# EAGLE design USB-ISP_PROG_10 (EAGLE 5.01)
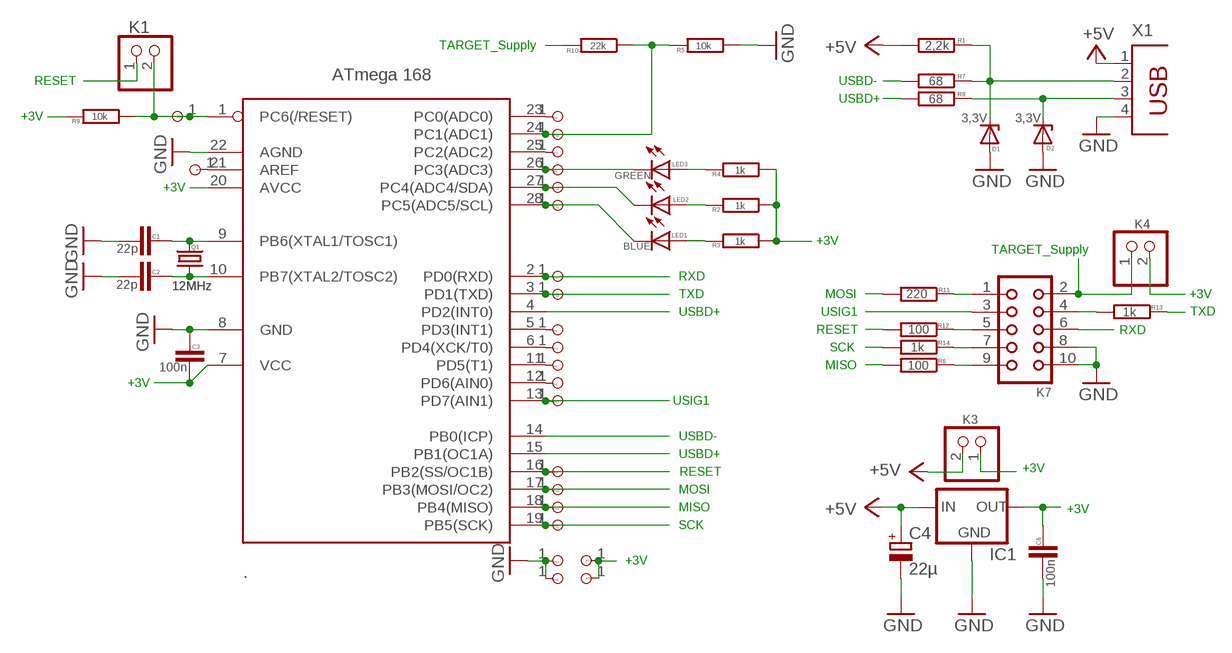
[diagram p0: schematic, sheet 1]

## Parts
.  ATmega 168  MEGA8-P  [DIL28-3]
C1  22p  C-EU025-024X044  [C025-024X044]
C2  22p  C-EU025-024X044  [C025-024X044]
C3  100n  C-EU025-024X044  [C025-024X044]
C4  22µ  CPOL-EU  [E2,5-11-L]
C6  100n  C-EU025-024X044  [C025-024X044]
D1  3,3V  ZENER-DIODEZD-7.5  [ZDIO-7.5]
D2  3,3V  ZENER-DIODEZD-7.5  [ZDIO-7.5]
IC1  78XXL-L  [78XXL-L]
JP1  PINHD-1X1  [1X01]
JP2  PINHD-1X1  [1X01]
JP3  PINHD-1X1  [1X01]
JP4  PINHD-1X1  [1X01]
JP5  PINHD-1X1  [1X01]
JP6  PINHD-1X1  [1X01]
JP7  PINHD-1X1  [1X01]
JP8  PINHD-1X1  [1X01]
JP9  PINHD-1X1  [1X01]
JP10  PINHD-1X1  [1X01]
JP11  PINHD-1X1  [1X01]
JP12  PINHD-1X1  [1X01]
JP13  PINHD-1X1  [1X01]
JP14  PINHD-1X1  [1X01]
JP15  PINHD-1X1  [1X01]
JP16  PINHD-1X1  [1X01]
JP17  PINHD-1X1  [1X01]
JP18  PINHD-1X1  [1X01]
JP19  PINHD-1X1  [1X01]
JP20  PINHD-1X1  [1X01]
JP21  PINHD-1X1  [1X01]
JP22  PINHD-1X1  [1X01]
JP23  PINHD-1X1  [1X01]
K1  PINHD-1X2  [1X02]
K3  PINHD-1X2  [1X02]
K4  PINHD-1X2  [1X02]
K7  CON10  [CON10]
LED1  BLUE  LED3MM  [LED3MM]
LED2  RED  LED3MM  [LED3MM]
LED3  GREEN  LED3MM  [LED3MM]
Q1  12MHz  CRYSTALHC49U70  [HC49U70]
R1  2,2k  R-EU_0207/07  [0207/07]
R2  1k  R-EU_0207/07  [0207/07]
R3  1k  R-EU_0207/07  [0207/07]
R4  1k  R-EU_0207/07  [0207/07]
R5  10k  R-EU_0207/07  [0207/07]
R6  100  R-EU_0207/07  [0207/07]
R7  68  R-EU_0207/07  [0207/07]
R8  68  R-EU_0207/07  [0207/07]
R9  10k  R-EU_0207/07  [0207/07]
R10  22k  R-EU_0207/07  [0207/07]
R11  220  R-EU_0207/07  [0207/07]
R12  100  R-EU_0207/17  [0207/17]
R13  1k  R-EU_0207/07  [0207/07]
R14  1k  R-EU_0207/07  [0207/07]
X1  PN87520-BKR  [PN87520-BKR]

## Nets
+3V: ..7(VCC) ..20(AVCC) C3.1 C6.2 IC1.OUT JP19.1 JP20.1 K3.1 K4.2 R2.1 R3.1 R4.1 R9.2
+5V: C4.+ IC1.IN K3.2 R1.2 X1.1
GND: ..8(GND) ..22(AGND) C1.1 C2.1 C3.2 C4.- C6.1 D1.A D2.A IC1.GND JP17.1 JP21.1 K7.8 K7.10 R5.1 X1.4
LED-BL: ..28(PC5(ADC5/SCL)) JP11.1 LED1.K(C)
LED-GN: ..26(PC3(ADC3)) JP9.1 LED3.K(C)
LED-RT: ..27(PC4(ADC4/SDA)) JP10.1 LED2.K(C)
MISO: ..18(PB4(MISO)) JP14.1 R6.2
MISO.: K7.9 R6.1
MOSI: ..17(PB3(MOSI/OC2)) JP13.1 R11.2
MOSI.: K7.1 R11.1
N$1: LED3.A R4.2
N$2: LED2.A R2.2
N$3: LED1.A R3.2
N$4: D1.C R1.1 R7.1 X1.2
N$5: D2.C R8.1 X1.3
N$13: ..23(PC0(ADC0)) JP1.1
N$14: ..9(PB6(XTAL1/TOSC1)) C1.2 Q1.2
N$15: ..10(PB7(XTAL2/TOSC2)) C2.2 Q1.1
N$16: ..1(PC6(/RESET)) JP18.1 K1.2 R9.1
N$17: ..25(PC2(ADC2)) JP2.1
N$18: ..24(PC1(ADC1)) JP16.1 R5.2 R10.1
N$19: ..5(PD3(INT1)) JP3.1
N$20: ..6(PD4(XCK/T0)) JP4.1
N$21: ..11(PD5(T1)) JP5.1
N$22: ..12(PD6(AIN0)) JP6.1
N$24: ..21(AREF) JP8.1
RESET: ..16(PB2(SS/OC1B)) JP7.1 K1.1 R12.2
RESET.: K7.5 R12.1
RXD: ..2(PD0(RXD)) JP22.1 K7.6
SCK: ..19(PB5(SCK)) JP15.1 R14.2
SCK.: K7.7 R14.1
TARGET_SUPPLY: K4.1 K7.2 R10.2
TXD: ..3(PD1(TXD)) JP23.1 R13.1
TXD,: K7.4 R13.2
USBD+: ..4(PD2(INT0)) ..15(PB1(OC1A)) R8.2
USBD-: ..14(PB0(ICP)) R7.2
USIG1: ..13(PD7(AIN1)) JP12.1 K7.3

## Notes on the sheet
- TARGET_Supply
- RESET | USBD-
- USBD+
- +3V
- +3V
- +3V | TARGET_Supply
- RXD
- TXD | MOSI | +3V
- USBD+ | USIG1 | TXD
- RESET | RXD
- SCK
- MISO
- +3V
- USIG1
- USBD-
- USBD+
- +3V
- RESET
- MOSI
- MISO | +3V
- SCK
- +3V

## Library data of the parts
. = atmel:MEGA8-P: MICROCONTROLLER 8 Kbytes FLASH 1 kbytes SRAM 512 bytes EEPROM USART 4-channel 10 bit ADC 2-channel 8 bit ADC Source: avr.lbr
C1-C3 C6 = rcl:C-EU: CAPACITOR, European symbol
C4 = rcl:CPOL-EU: POLARIZED CAPACITOR, European symbol
D1 D2 = diode:ZENER-DIODE: Z-Diode
IC1 = v-reg:78XXL-L: VOLTAGE REGULATOR
JP1-JP23 = pinhead 02:PINHD-1X1: PIN HEADER
K1 K3 K4 = pinhead:PINHD-1X2: PIN HEADER
K7 = con-harting:CON10: CONNECTOR
LED1-LED3 = led:LED: LED
Q1 = crystal:CRYSTAL: CRYSTAL
R1-R14 = rcl:R-EU_: RESISTOR, European symbol
X1 = con-berg:PN87520-BKR: BERG USB connector

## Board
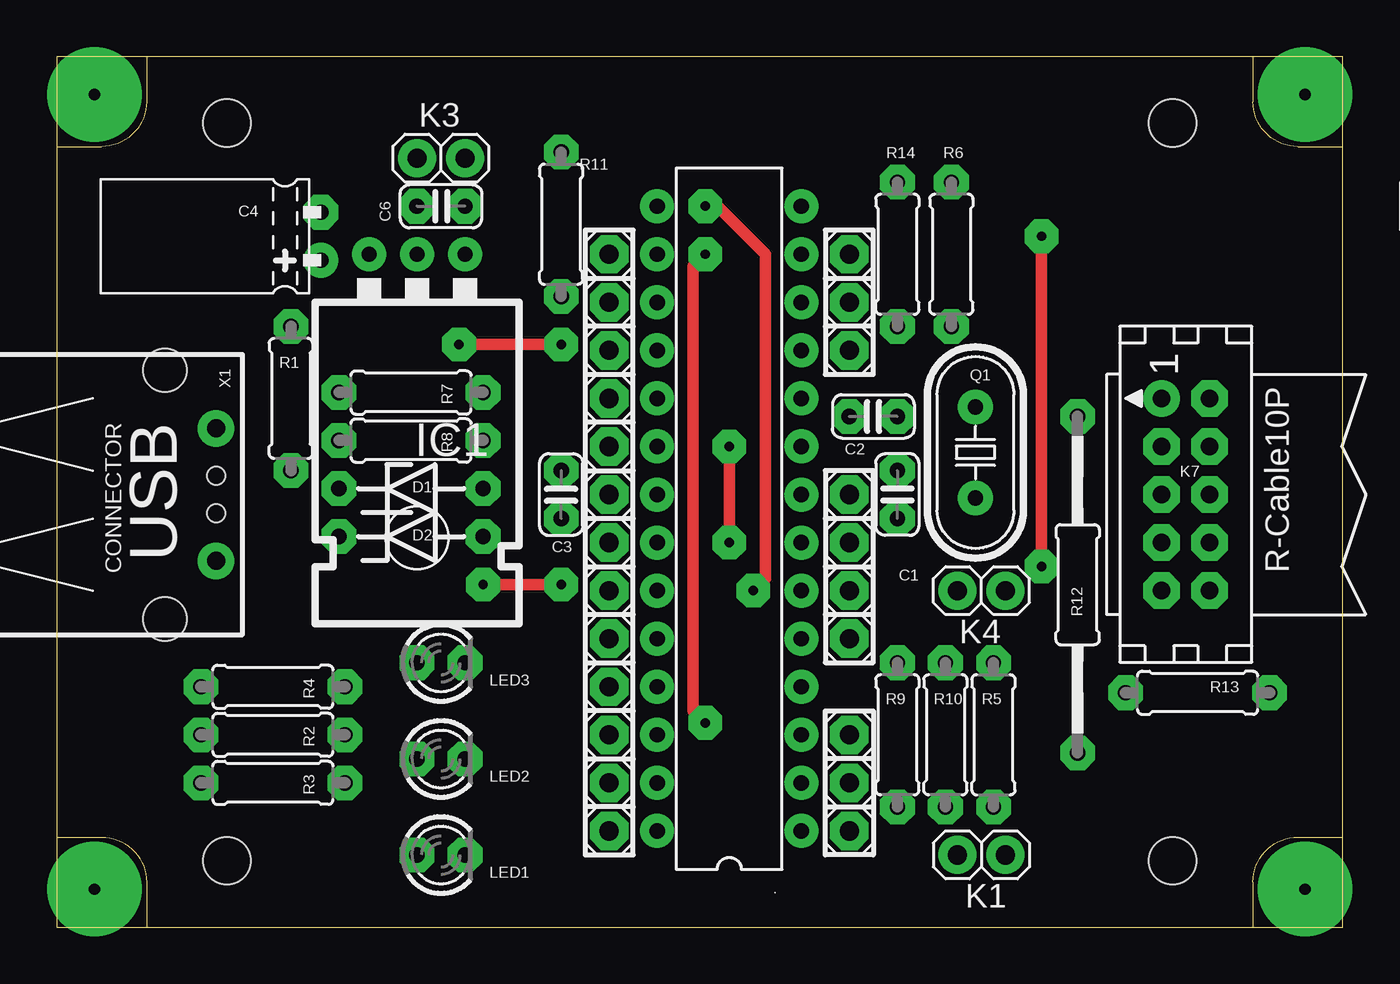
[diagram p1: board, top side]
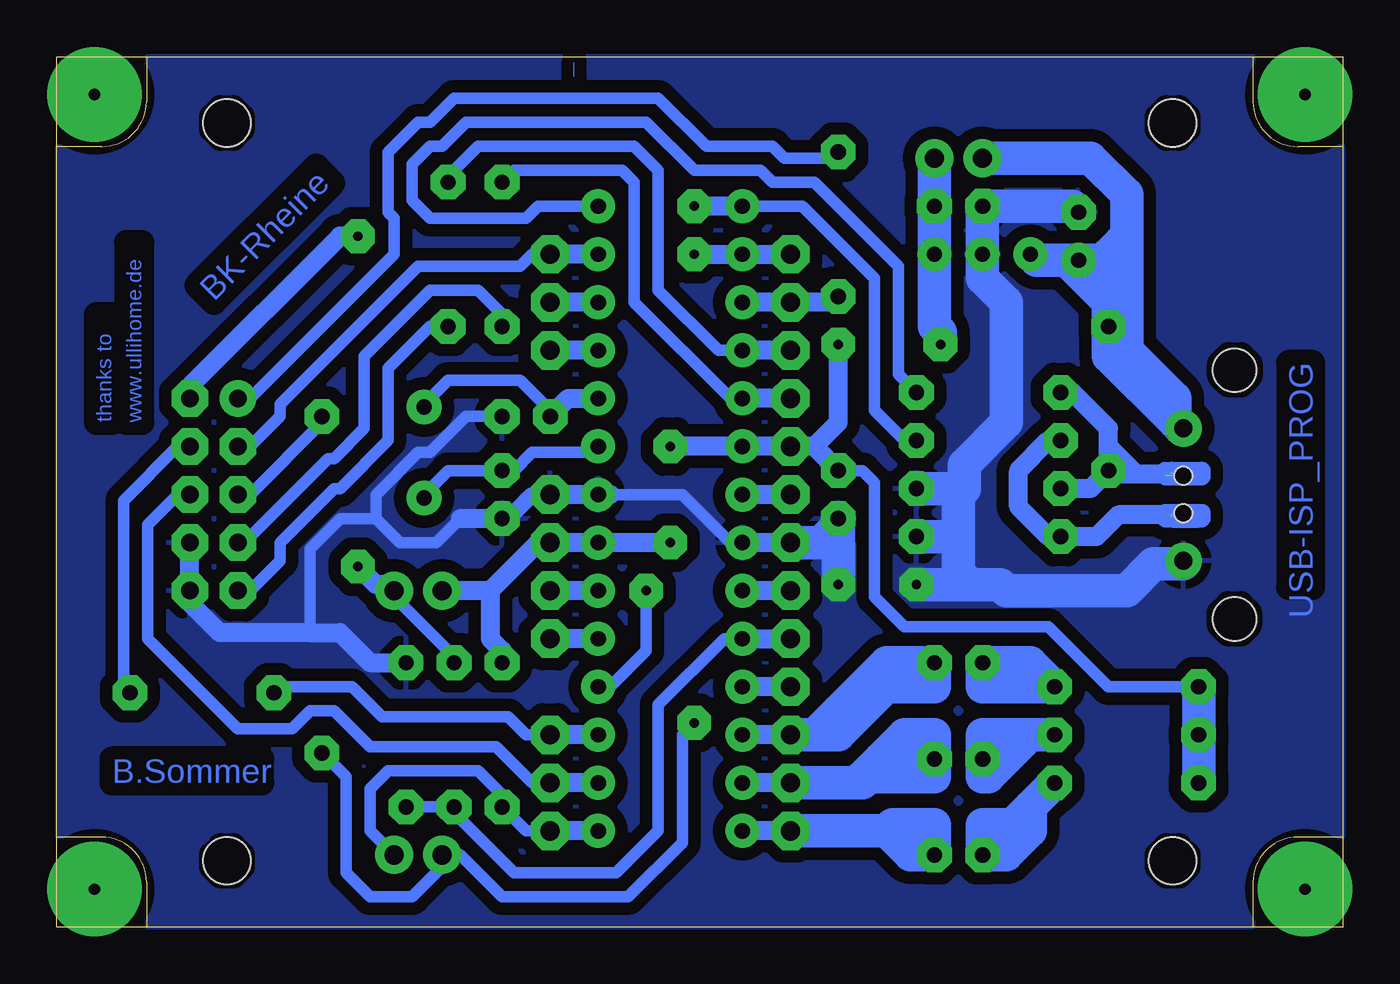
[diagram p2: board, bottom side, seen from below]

Size 68 x 46 mm. Coordinates in mm from the lower left corner, seen from the top.
Outline: 4.75,0 0,0 0,4.75
Outline: 4.75,0 63.25,0
Outline: 63.25,0 68,0 68,4.75
Outline: 68,4.75 68,41.25
Outline: 68,41.25 68,46 63.25,46
Outline: 63.25,46 4.75,46
Outline: 4.75,46 0,46 0,41.25
Outline: 0,41.25 0,4.75
Outline: 4.75,0 4.75,2.38 arc90 2.38,4.75 0,4.75
Outline: 0,41.25 2.38,41.25 arc90 4.75,43.62 4.75,46
Outline: 63.25,46 63.25,43.62 arc90 65.62,41.25 68,41.25
Outline: 68,4.75 65.62,4.75 arc90 63.25,2.38 63.25,0
Copper layers (1*16): Top 0.035mm / dielectric 1.5mm / Bottom 0.035mm
Design rules "sommer_02_Ãtzen": minimum track width 24mil, minimum drill 0.5mm, track to track 26mil, track to pad 26mil, pad to pad 20mil, via to via 20mil, smd to smd 8mil, copper to edge 0mil, drill to drill 8mil, minimum pad ring 20mil, minimum via ring 20mil, stop-mask expansion 4mil, vias tented up to drill 0mil, thermal gap 20mil
Holes 2.5 mm at 9,3.5 9,42.5 59,3.5 59,42.5

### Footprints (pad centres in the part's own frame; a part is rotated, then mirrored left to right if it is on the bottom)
DIL28-3 = drill 0.813 long: 1 -16.51,-3.81; 2 -13.97,-3.81; 3 -11.43,-3.81; 4 -8.89,-3.81; 5 -6.35,-3.81; 6 -3.81,-3.81; 7 -1.27,-3.81; 8 1.27,-3.81; 9 3.81,-3.81; 10 6.35,-3.81; 11 8.89,-3.81; 12 11.43,-3.81; 13 13.97,-3.81; 14 16.51,-3.81; 15 16.51,3.81; 16 13.97,3.81; 17 11.43,3.81; 18 8.89,3.81; 19 6.35,3.81; 20 3.81,3.81; 21 1.27,3.81; 22 -1.27,3.81; 23 -3.81,3.81; 24 -6.35,3.81; 25 -8.89,3.81; 26 -11.43,3.81; 27 -13.97,3.81; 28 -16.51,3.81
C025-024X044 = drill 0.813 octagon: 1 -1.27,0; 2 1.27,0
E2,5-11-L = drill 0.813 pad 1.6 round: + 0,-1.27 | drill 0.813 pad 1.6 octagon: - 0,1.27
ZDIO-7.5 = drill 0.813 octagon: A 3.81,0; C -3.81,0
78XXL-L = drill 0.8 long: GND 0,3.81; IN -2.54,3.81; OUT 2.54,3.81
1X01 = drill 1.016 octagon: 1 0,0
1X02 = drill 1.016 long: 1 -1.27,0; 2 1.27,0
CON10 = drill 0.914 round: 1 -5.08,-1.27 | drill 0.914 octagon: 2 -5.08,1.27; 3 -2.54,-1.27; 4 -2.54,1.27; 5 0,-1.27; 6 0,1.27; 7 2.54,-1.27; 8 2.54,1.27; 9 5.08,-1.27; 10 5.08,1.27
LED3MM = drill 0.813 octagon: A -1.27,0; K 1.27,0
HC49U70 = drill 0.813 round: 1 -2.413,0; 2 2.413,0
0207/07 = drill 0.813 octagon: 1 -3.81,0; 2 3.81,0
0207/17 = drill 0.813 octagon: 1 -8.89,0; 2 8.89,0
PN87520-BKR = drill 0.95 long: 1 -3.5,2.71; 4 3.5,2.71 | smd 0.203 x 0.406 bottom: 2 -1.079,3.504; 3 1.079,3.504 | hole 0.95: -1,2.71; 0.991,2.71 | hole 2.3: -6.57,0; 6.57,0

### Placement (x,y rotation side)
.  35.56,21.59 90 top
C1  44.45,22.86 90 top
C2  43.18,26.99 180 top
C3  26.67,22.86 270 top
C4  13.97,36.51 0 top
C6  20.32,38.1 0 top
D1  18.73,23.18 0 top
D2  18.73,20.64 0 top
IC1  19.05,31.75 0 top
JP1  29.21,17.78 0 top
JP2  29.21,12.7 0 top
JP3  41.91,15.24 0 top
JP4  41.91,17.78 0 top
JP5  41.91,30.48 0 top
JP6  41.91,33.02 0 top
JP7  29.21,35.56 0 top
JP8  29.21,22.86 0 top
JP9  29.21,10.16 0 top
JP10  29.21,7.62 0 top
JP11  29.21,5.08 0 top
JP12  41.91,35.56 0 top
JP13  29.21,33.02 0 top
JP14  29.21,30.48 0 top
JP15  29.21,27.94 0 top
JP16  29.21,15.24 0 top
JP17  29.21,20.32 0 top
JP18  41.91,5.08 0 top
JP19  29.21,25.4 0 top
JP20  41.91,20.32 0 top
JP21  41.91,22.86 0 top
JP22  41.91,7.62 0 top
JP23  41.91,10.16 0 top
K1  48.9,3.81 0 top
K3  20.32,40.64 180 top
K4  48.9,17.78 180 top
K7  59.69,22.86 270 top
LED1  20.32,3.81 0 top
LED2  20.32,8.89 0 top
LED3  20.32,13.97 0 top
Q1  48.58,25.08 270 top
R1  12.38,27.94 90 top
R2  11.43,10.16 0 top
R3  11.43,7.62 0 top
R4  11.43,12.7 0 top
R5  49.53,10.16 270 top
R6  47.31,35.56 90 top
R7  18.73,28.26 0 top
R8  18.73,25.72 0 top
R9  44.45,10.16 90 top
R10  46.99,10.16 90 top
R11  26.67,37.15 270 top
R12  53.98,18.1 270 top
R13  60.33,12.38 0 top
R14  44.45,35.56 90 top
X1  5.71,22.86 270 top

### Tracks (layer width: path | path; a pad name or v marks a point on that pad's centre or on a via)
+3V  (via drill 0.5 pad 1.78)
  Top 0.61: v35.56,25.4 v35.56,20.32 | v26.67,30.8 v21.27,30.8
  Bottom 0.61: 44.45,14.61 R9.2 | C3.1 25.4,24.13 24.77,23.5 24.77,17.46 23.18,15.88 15.56,15.88 12.38,12.7 R4.1
  Bottom 1.016: v35.56,25.4 ..20 JP19.1 27.94,25.4 | v35.56,20.32 ..7 JP20.1 42.55,20.32 45.09,17.78 | 45.09,17.78 45.09,15.24 44.45,14.61 | v26.67,30.8 26.67,26.67 27.94,25.4 | C3.1 27.94,25.4 | 45.09,17.78 K4.2
  Bottom 1.778: K3.1 C6.2 IC1.OUT 21.59,31.75 21.27,31.43 v21.27,30.8 | R4.1 R2.1 R3.1
+5V
  Bottom 1.778: 11.43,36.83 11.43,36.51 11.75,36.2 | 11.43,36.83 11.43,38.73 13.34,40.64 K3.2 | 8.57,26.35 8.56,26.36 X1.1 8.58,26.36 8.89,26.67 | 14.61,35.24 C4.+ 12.7,35.24 11.75,36.2 | 8.89,26.67 12.38,30.16 R1.2 12.38,33.02 | 12.38,33.02 12.38,35.56 11.75,36.2 | 11.43,36.83 11.43,30.48 8.89,27.94 8.89,26.67 | 12.38,33.02 14.61,35.24 | 14.61,35.24 16.19,35.24 IC1.IN
GND  (via drill 0.5 pad 1.78)
  Top 0.61: v22.54,18.1 v26.67,18.1
  Bottom 0.61: ..22 32.38,20.32 34.92,22.86 38.73,22.86 | C3.2 26.67,20.95 | 46.67,21.59 47.94,20.32 49.85,20.32 51.12,21.59 | C2.1 46.35,26.99 48.26,25.08 48.9,25.08 51.12,22.86 51.12,21.59 | 54.61,15.56 54.61,20 53.02,21.59 51.12,21.59
  Bottom 0.813: JP21.1 42.86,22.86 44.13,21.59
  Bottom 1.016: 38.73,22.86 ..8 JP21.1 | K7.8 K7.10 60.96,17.14 59.37,15.56 54.61,15.56 53.02,15.56 51.44,13.97 R5.1 | JP17.1 ..22 | 44.13,21.59 C1.1 46.67,21.59
  Bottom 1.778: C4.- 14.29,38.1 C6.1 IC1.GND 19.05,34.29 17.78,33.02 17.78,26.67 20,24.45 20,23.18 20.32,23.18 | JP17.1 27.62,20.32 26.99,20.95 | 8.43,19.2 10.01,19.2 11.43,17.78 17.78,17.78 18.1,18.1 20,18.1 | 20,18.1 v22.54,18.1 | v26.67,18.1 C3.2 | 20.32,23.18 D1.A | 20,18.1 20,18.41 20.32,18.73 20.32,20.32 | D2.A 20.64,20.64 20.32,20.32 | 20.32,20.32 20.32,23.18
  pour Bottom: 3.49,4.76 4.76,3.49 4.76,0 63.18,0 63.18,3.49 64.45,4.76 67.94,4.76 67.94,41.27 64.45,41.27 63.18,42.55 63.18,46.04 4.76,46.04 4.76,42.55 3.49,41.27 0,41.27 0,4.76
LED-BL
  Bottom 1.016: JP11.1 ..28
  Bottom 1.778: 24.13,5.08 22.86,5.08 LED1.K | 24.13,5.08 JP11.1 | 24.13,5.08 22.86,3.81 LED1.K | LED1.K 21.59,5.4 23.81,5.4 24.13,5.08
LED-GN
  Bottom 1.016: JP9.1 ..26
  Bottom 1.778: 27.94,10.16 JP9.1 | 22.86,13.97 24.13,12.7 | 24.13,12.7 26.67,10.16 | 22.86,13.97 LED3.K 21.59,12.7 24.13,12.7 | 22.86,13.97 24.13,13.97 26.67,11.43 | 26.67,11.43 26.67,10.16 | 26.67,10.16 27.94,10.16 | 26.67,11.43 27.94,10.16
LED-RT
  Bottom 1.016: JP10.1 ..27
  Bottom 1.778: LED2.K 24.45,8.89 | 24.45,8.89 25.4,7.94 | 25.4,7.94 25.4,7.62 JP10.1 | LED2.K 21.59,10.16 23.18,10.16 24.45,8.89 | LED2.K 21.59,7.94 25.4,7.94
MISO
  Bottom 0.61: ..18 33.02,30.48 36.2,33.66 36.2,40.01 37.47,41.27 45.72,41.27 47.31,39.69 R6.2
  Bottom 1.016: JP14.1 ..18
MISO.
  Bottom 0.61: R6.1 48.26,31.75 50.48,29.53 50.48,25.72 53.02,23.18 53.34,23.18 56.2,20.32 56.2,19.37 57.78,17.78 K7.9
MOSI
  Bottom 0.61: R11.2 26.99,33.02
  Bottom 1.016: ..17 JP13.1 26.99,33.02
MOSI.
  Bottom 0.61: R11.1 26.99,40.64 29.53,40.64 30.16,41.27 33.66,41.27 36.2,43.81 46.99,43.81 48.26,42.55 48.9,42.55 50.48,40.96 50.48,37.78 50.16,37.47 50.16,35.56 57.78,27.94 K7.1
N$1
  Bottom 1.778: R4.2 16.51,13.97 LED3.A 19.05,12.7 R4.2
N$2
  Bottom 1.778: R2.2 16.51,10.16 | 16.51,10.16 17.78,10.16 | 17.78,10.16 LED2.A | 17.78,10.16 19.05,10.16 LED2.A | LED2.A 19.05,7.94 18.73,7.94 16.51,10.16
N$3
  Bottom 1.778: LED1.A 17.46,5.4 | 17.46,5.4 19.05,5.4 LED1.A | 17.46,5.4 16.51,6.35 | 16.51,6.35 R3.2 | LED1.A 17.78,3.81 16.51,5.08 16.51,6.35
N$4
  Bottom 1.016: R1.1 13.34,23.18 D1.C | R7.1 14.29,28.26 12.38,26.35 12.38,25.4 | R1.1 12.38,25.4 | 12.38,25.4 11.11,24.13 | X1.2 12.19,23.94 R1.1
N$5
  Bottom 1.016: R8.1 15.56,25.72 17.14,24.13 17.14,22.23 15.56,20.64 D2.C 13.02,20.64 12.06,21.59 11.87,21.78 X1.3
N$6  (via drill 0.9 pad 1.93)
  other vias: 72.39,38.1
N$7  (via drill 0.9 pad 1.93)
  other vias: 76.2,38.1
N$10
  pour Bottom: 1.27,6.35 5.08,5.08 6.35,1.27 60.96,1.27 62.23,5.08 66.04,6.35 66.04,39.37 62.23,40.64 60.96,44.45 6.35,44.45 5.08,40.64 1.27,39.37
N$12
  Bottom 0: 40.64,44.95 40.64,45.72
N$13
  Bottom 1.016: JP1.1 ..23
N$14
  Bottom 0.61: Q1.2 48.58,22.86 47.31,24.13 C1.2 43.81,24.13 42.86,25.08 39.69,25.08 ..9
N$15
  Bottom 0.61: C2.2 41.91,27.3 43.5,28.89 47.31,28.89 48.58,27.62 Q1.1
  Bottom 1.016: ..10 40.96,27.94 C2.2
N$16
  Bottom 0.61: ..1 JP18.1 43.18,5.08 R9.1 44.45,6.99 45.72,8.26 50.48,8.26 51.44,7.3 51.44,5.08 K1.2
  Bottom 1.016: ..1 JP18.1
N$17
  Bottom 1.016: JP2.1 ..25
N$18
  Bottom 0.61: ..24 32.7,15.24 36.2,11.75 36.2,5.08 38.42,2.86 43.81,2.86 46.99,6.03 R10.1 R5.2
  Bottom 1.016: ..24 JP16.1
N$19
  Bottom 1.016: ..5 JP3.1
N$20
  Bottom 1.016: ..6 JP4.1
N$21
  Bottom 1.016: ..11 JP5.1
N$22
  Bottom 1.016: ..12 JP6.1
N$23  (via drill 0.6 pad 1.27)
  other vias: 9,3.5
N$24
  Bottom 1.016: JP8.1 ..21
N$25  (via drill 0.6 pad 1.27)
  other vias: 59,3.5
N$26  (via drill 0.6 pad 1.27)
  other vias: 59,42.5
N$27  (via drill 0.6 pad 1.27)
  other vias: 9,42.5
N$28  (via drill 0.6 pad 1.27)
  other vias: 5.72,16.29
N$29  (via drill 0.6 pad 1.27)
  other vias: 5.71,29.45
N$30  (via drill 0.6 pad 5)
  other vias: 2,44
N$31  (via drill 0.6 pad 5)
  other vias: 2,2
N$32  (via drill 0.6 pad 5)
  other vias: 66,44
N$33  (via drill 0.6 pad 5)
  other vias: 66,2
RESET  (via drill 0.5 pad 1.78)
  Top 0.61: v34.29,35.56 33.66,34.92 33.66,11.43 v34.29,10.79
  Bottom 0.61: v34.29,10.79 34.92,10.16 34.92,4.45 37.78,1.59 44.45,1.59 46.67,3.81 K1.1 47.62,3.17 49.21,1.59 51.44,1.59 52.7,2.86 52.7,7.94 R12.2
  Bottom 1.016: JP7.1 ..16 v34.29,35.56
RESET.
  Bottom 0.61: R12.1 53.98,26.67 57.78,22.86 K7.5
RXD
  Bottom 0.61: K7.6 61.59,22.86 63.18,21.27 63.18,15.24 58.42,10.48 55.56,10.48 54.61,11.43 53.34,11.43 51.44,9.53 44.77,9.53 42.86,7.62 JP22.1
  Bottom 1.016: ..2 JP22.1
SCK
  Bottom 0.61: ..19 32.38,27.94 37.47,33.02 37.47,39.37 38.1,40.01 43.81,40.01 R14.2
  Bottom 1.016: JP15.1 ..19
SCK.
  Bottom 0.61: R14.1 44.45,32.38 45.72,33.66 48.26,33.66 51.75,30.16 51.75,26.35 53.34,24.77 53.66,24.77 58.1,20.32 K7.7
TARGET_SUPPLY  (via drill 0.5 pad 1.78)
  Top 0.61: v52.07,19.05 v52.07,36.51
  Bottom 0.61: R10.2 46.99,14.29 50.16,17.46 K4.1
  Bottom 1.016: K7.2 60.96,28.57 53.02,36.51 v52.07,36.51 | K4.1 50.48,18.1 51.12,18.1 v52.07,19.05
TXD
  Bottom 0.61: JP23.1 43.18,10.16 44.13,11.11 50.8,11.11 52.39,12.7 55.88,12.7 56.2,12.38 R13.1
  Bottom 1.016: ..3 JP23.1
TXD,
  Bottom 0.61: R13.2 64.45,12.7 64.45,22.54 61.59,25.4 K7.4
USBD+  (via drill 0.5 pad 1.78)
  Top 0.61: v34.29,38.1 34.92,38.1 37.47,35.56 37.47,18.41 v36.83,17.78
  Bottom 0.61: v36.83,17.78 36.83,14.61 38.73,12.7 ..4 | ..15 28.57,38.1 24.77,34.29 24.77,27.3 23.18,25.72 R8.2
  Bottom 1.016: ..15 v34.29,38.1
USBD-
  Bottom 0.61: ..14 42.55,38.1 43.18,37.47 48.26,37.47 49.21,38.42 49.21,40.32 48.26,41.27 47.62,41.27 46.35,42.55 36.83,42.55 34.29,40.01 30.8,40.01 30.16,39.37 27.94,39.37 23.5,34.92 23.5,29.21 R7.2
USIG1
  Bottom 0.61: JP12.1 42.86,35.56 43.5,34.92 48.9,34.92 56.2,27.62 56.2,26.99 57.78,25.4 K7.3
  Bottom 1.016: ..13 JP12.1

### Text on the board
Bottom: BK-Rheine | USB-ISP_PROG | www.ullihome.de | thanks to | B.Sommer
tPlace: Buchse | Stift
